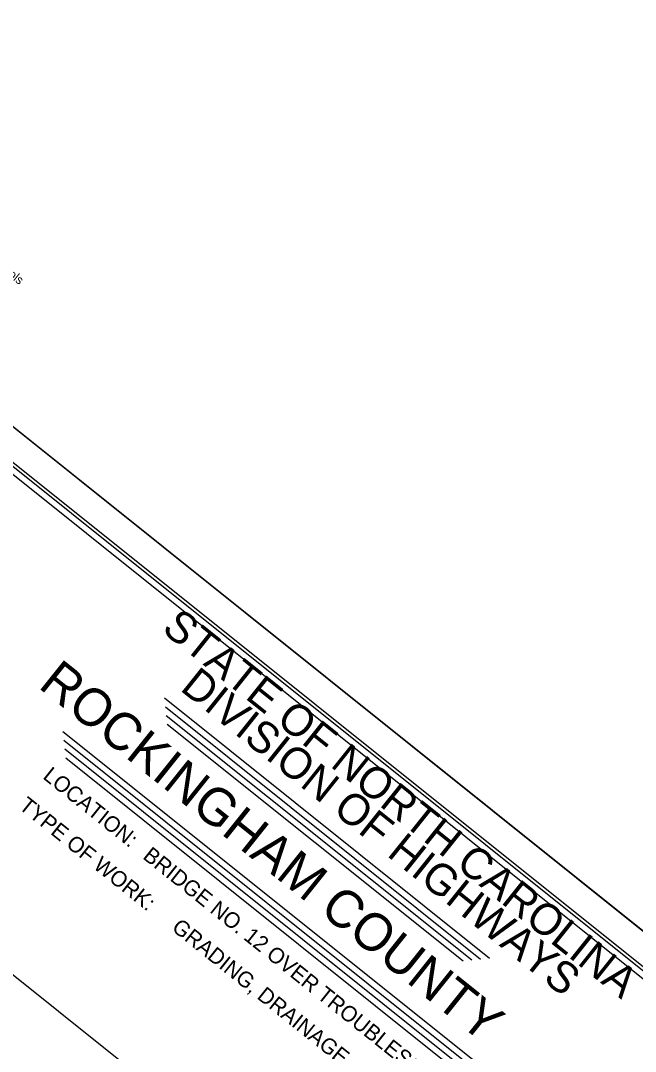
# Model space of a CAD drawing. Extents: x 1732765 to 1738218, y 913652 to 917906.
# Drawn here: x 1734963 to 1735946, y 916081 to 917728 of the extents above; entities that cross this region are included whole.
import ezdxf

# ---------------------------------------------------------------- set-up
doc = ezdxf.new("R2010")
doc.units = 0
for name, color, linetype in [('Prop Rip Rap Related Quantities Text', 7, 'Continuous'), ('Sheet Cutting Line CELL', 7, 'Continuous'), ('Sheet Data Field CELL', 7, 'Continuous'), ('Sheet Plot Border Inside CELL', 7, 'Continuous'), ('Sheet Title CELL', 7, 'Continuous')]:
    doc.layers.add(name, color=color, linetype=linetype)

msp = doc.modelspace()

# ---------------------------------------------------------------- linework, layer by layer
at = {"layer": 'Prop Rip Rap Related Quantities Text'}
msp.add_lwpolyline([(1735803.5, 915520.4), (1734632.4, 916457.7), (1733985, 915648.7)], dxfattribs=at)
at = {"layer": 'Sheet Cutting Line CELL'}
msp.add_line((1734139.9, 917728.5), (1736769.5, 915624), dxfattribs=at)
at = {"layer": 'Sheet Data Field CELL'}
msp.add_lwpolyline([(1736769.5, 915624), (1734139.9, 917728.5), (1732765.3, 916010.8), (1735394.8, 913906.4)], close=True, dxfattribs=at)
at = {"layer": 'Sheet Plot Border Inside CELL'}
msp.add_lwpolyline([(1732813.6, 916029.6), (1735415.9, 913947), (1736734.4, 915594.6), (1734132.1, 917677.2)], close=True, dxfattribs=at)
at = {"layer": 'Sheet Title CELL'}
for p, q in [((1735193.2, 916645.9), (1735712.8, 916230.1)), ((1735194.8, 916631.9), (1735698.7, 916228.5)), ((1735196.3, 916617.8), (1735684.7, 916227)), ((1735197.9, 916603.7), (1735670.6, 916225.4)), ((1735030.9, 916592.4), (1735696.1, 916060)), ((1735032.4, 916578.3), (1735682, 916058.5)), ((1735034, 916564.3), (1735668, 916056.9)), ((1735035.5, 916550.2), (1735653.9, 916055.3))]:
    msp.add_line(p, q, dxfattribs=at)
for points in [[(1736696.1, 915618.7), (1734385, 917468.3)], [(1736682, 915617.2), (1734464.7, 917391.7)]]:
    msp.add_lwpolyline(points, dxfattribs=at)

# ---------------------------------------------------------------- texts
at = {"layer": 'Sheet Data Field CELL'}
for s, height, p in [('ROCKINGHAM COUNTY', 60, (1734990, 916663.3)), ('BRIDGE NO. 12 OVER TROUBLESOME CREEK ON SR 2343', 25, (1735157.2, 916390.2)), ('GRADING, DRAINAGE, PAVING AND CULVERT', 25, (1735203.4, 916275.7))]:
    msp.add_text(s, height=height, rotation=321.3297, dxfattribs=at).set_placement(p)
at = {"layer": 'Sheet Title CELL'}
for s, height, p in [('See Sheet 1-B For Conventional Symbols', 13.999, (1734690.9, 917522.3)), ('STATE OF NORTH CAROLINA', 50, (1735187.2, 916753)), ('DIVISION OF HIGHWAYS', 50, (1735216.7, 916659)), ('LOCATION: ', 25, (1734997.5, 916518.1)), ('TYPE OF WORK:', 25, (1734959.1, 916470))]:
    msp.add_text(s, height=height, rotation=321.3297, dxfattribs=at).set_placement(p)

doc.saveas('drawing.dxf')
